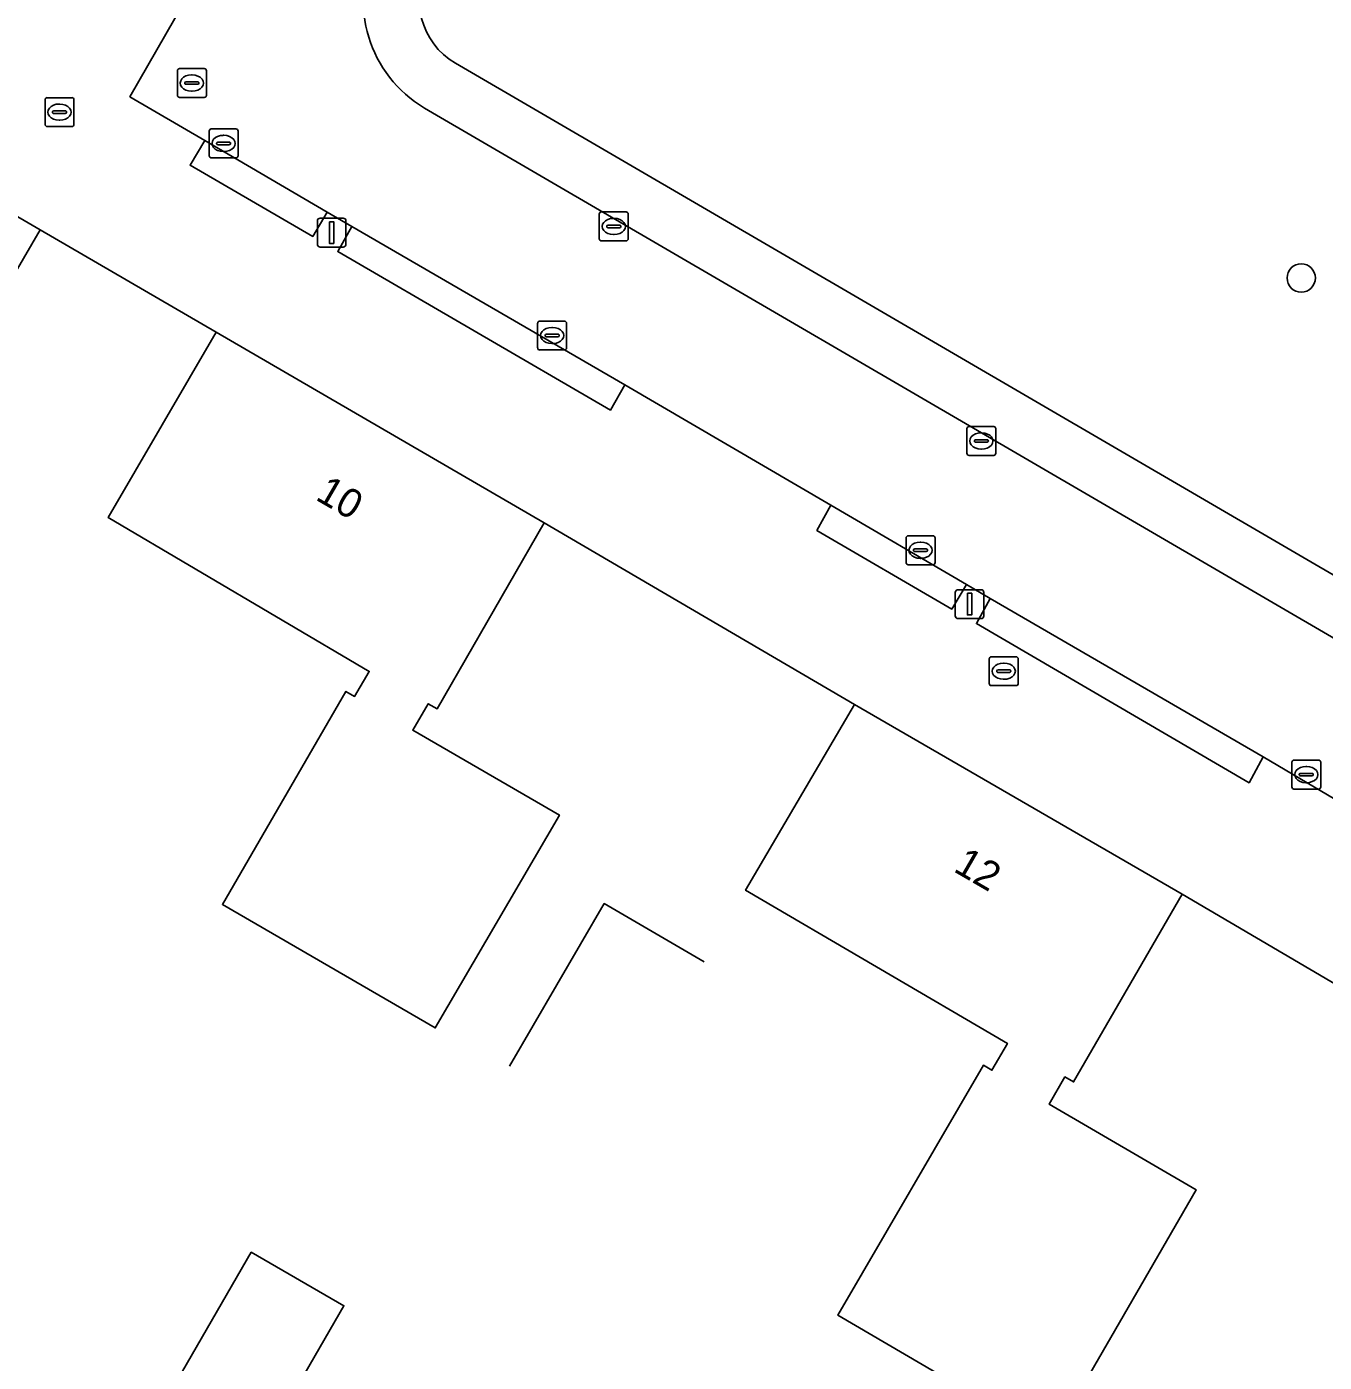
# Model space of a CAD drawing. Extents: x 156502 to 159075, y 384229 to 386100.
# Drawn here: x 157106.1 to 157150.95, y 385818.95 to 385865.1 of the extents above; entities that cross this region are included whole.
import ezdxf

# ---------------------------------------------------------------- set-up
doc = ezdxf.new("R2010")
doc.units = 0
for name, color, linetype in [('IMGEO_Boom', 7, 'Continuous'), ('IMGEO_Erf', 7, 'Continuous'), ('IMGEO_Groenvoorziening', 7, 'Continuous'), ('IMGEO_Haag', 7, 'Continuous'), ('IMGEO_Hek', 7, 'Continuous'), ('IMGEO_Kolk', 7, 'Continuous'), ('IMGEO_Lichtmast', 7, 'Continuous'), ('IMGEO_Muur', 7, 'Continuous'), ('IMGEO_Pand', 7, 'Continuous'), ('IMGEO_Pand_nummerreeks', 7, 'Continuous'), ('IMGEO_Parkeervlak_open', 7, 'Continuous'), ('IMGEO_Rijbaan_lokaal_open', 7, 'Continuous'), ('IMGEO_Rioolput', 7, 'Continuous'), ('IMGEO_Voetpad_open', 7, 'Continuous')]:
    doc.layers.add(name, color=color, linetype=linetype)

msp = doc.modelspace()

# ---------------------------------------------------------------- linework, layer by layer
at = {"layer": 'IMGEO_Boom'}
msp.add_circle((157150.156, 385856.417), 0.489, dxfattribs=at)
at = {"layer": 'IMGEO_Erf'}
msp.add_lwpolyline([(157155.595, 385829.52), (157146.045, 385835.121), (157142.29, 385828.637), (157141.989, 385828.812), (157141.44, 385827.871), (157146.528, 385824.906), (157141.519, 385816.264), (157134.144, 385820.573), (157139.17, 385829.213), (157139.464, 385829.042), (157140.002, 385829.967), (157130.951, 385835.263), (157134.715, 385841.68), (157123.992, 385847.954), (157120.284, 385841.529), (157119.981, 385841.704), (157119.443, 385840.792), (157124.514, 385837.857), (157120.221, 385830.506), (157112.866, 385834.77), (157117.135, 385842.132), (157117.437, 385841.957), (157117.939, 385842.822), (157108.916, 385848.145), (157112.648, 385854.542), (157106.562, 385858.084), (157102.808, 385851.646)], dxfattribs=at)
msp.add_lwpolyline([(157111.485, 385818.64), (157113.86, 385822.753), (157117.067, 385820.902), (157114.692, 385816.789)], close=True, dxfattribs=at)
at = {"layer": 'IMGEO_Groenvoorziening'}
msp.add_lwpolyline([(157120.919, 385863.835), (157175.135, 385832.241)], dxfattribs=at)
for points in [[(157116.486, 385858.694), (157112.261, 385861.167), (157111.749, 385860.312), (157115.987, 385857.851)], [(157117.345, 385858.202), (157116.851, 385857.331), (157126.279, 385851.85), (157126.778, 385852.73)], [(157138.584, 385845.831), (157133.897, 385848.562), (157133.418, 385847.696), (157138.076, 385844.975)], [(157139.408, 385845.347), (157138.927, 385844.474), (157148.354, 385838.978), (157148.842, 385839.867)]]:
    msp.add_lwpolyline(points, close=True, dxfattribs=at)
msp.add_arc((157122.202, 385866.019), 2.533, 149.5838, 239.5596, dxfattribs=at)
at = {"layer": 'IMGEO_Haag'}
for points in [[(157116.486, 385858.694), (157112.261, 385861.167), (157111.749, 385860.312), (157115.987, 385857.851)], [(157117.345, 385858.202), (157116.851, 385857.331), (157126.279, 385851.85), (157126.778, 385852.73)], [(157138.584, 385845.831), (157133.897, 385848.562), (157133.418, 385847.696), (157138.076, 385844.975)], [(157139.408, 385845.347), (157138.927, 385844.474), (157148.354, 385838.978), (157148.842, 385839.867)]]:
    msp.add_lwpolyline(points, close=True, dxfattribs=at)
at = {"layer": 'IMGEO_Hek'}
for points in [[(157112.648, 385854.542), (157106.562, 385858.084)], [(157134.715, 385841.68), (157123.992, 385847.954)], [(157155.595, 385829.52), (157146.045, 385835.121)]]:
    msp.add_lwpolyline(points, dxfattribs=at)
at = {"layer": 'IMGEO_Kolk'}
for p, q in [((157112.407, 385860.641), (157112.407, 385861.493)), ((157112.482, 385861.567), (157113.334, 385861.567)), ((157112.895, 385861.347), (157112.92, 385861.347)), ((157113.408, 385861.493), (157113.408, 385860.641)), ((157112.666, 385861.061), (157112.666, 385861.073)), ((157113.104, 385861.024), (157112.706, 385861.024)), ((157112.709, 385861.11), (157113.107, 385861.11)), ((157113.15, 385861.073), (157113.15, 385861.061)), ((157113.334, 385860.567), (157112.482, 385860.567)), ((157112.918, 385860.787), (157112.893, 385860.787)), ((157125.894, 385857.772), (157125.894, 385858.624)), ((157125.969, 385858.698), (157126.821, 385858.698)), ((157126.895, 385858.624), (157126.895, 385857.772)), ((157126.153, 385858.192), (157126.153, 385858.204)), ((157126.591, 385858.155), (157126.193, 385858.155)), ((157126.196, 385858.241), (157126.594, 385858.241)), ((157126.382, 385858.478), (157126.407, 385858.478)), ((157126.637, 385858.204), (157126.637, 385858.192)), ((157126.821, 385857.698), (157125.969, 385857.698)), ((157126.405, 385857.918), (157126.38, 385857.918)), ((157123.763, 385854.003), (157123.763, 385854.855)), ((157123.838, 385854.929), (157124.69, 385854.929)), ((157124.764, 385854.855), (157124.764, 385854.003)), ((157124.022, 385854.423), (157124.022, 385854.435)), ((157124.46, 385854.386), (157124.062, 385854.386)), ((157124.065, 385854.472), (157124.463, 385854.472)), ((157124.251, 385854.709), (157124.276, 385854.709)), ((157124.506, 385854.435), (157124.506, 385854.423)), ((157124.69, 385853.929), (157123.838, 385853.929)), ((157124.274, 385854.149), (157124.249, 385854.149)), ((157138.599, 385850.359), (157138.599, 385851.211)), ((157138.674, 385851.285), (157139.526, 385851.285)), ((157139.6, 385851.211), (157139.6, 385850.359)), ((157138.858, 385850.779), (157138.858, 385850.791)), ((157139.296, 385850.742), (157138.898, 385850.742)), ((157138.901, 385850.828), (157139.299, 385850.828)), ((157139.087, 385851.065), (157139.112, 385851.065)), ((157139.342, 385850.791), (157139.342, 385850.779)), ((157139.526, 385850.285), (157138.674, 385850.285)), ((157139.11, 385850.505), (157139.085, 385850.505)), ((157136.497, 385846.584), (157136.497, 385847.436)), ((157136.572, 385847.51), (157137.424, 385847.51)), ((157137.498, 385847.436), (157137.498, 385846.584)), ((157136.756, 385847.004), (157136.756, 385847.016)), ((157136.799, 385847.053), (157137.197, 385847.053)), ((157136.985, 385847.29), (157137.01, 385847.29)), ((157137.24, 385847.016), (157137.24, 385847.004)), ((157137.424, 385846.51), (157136.572, 385846.51)), ((157137.194, 385846.967), (157136.796, 385846.967)), ((157137.008, 385846.73), (157136.983, 385846.73)), ((157149.831, 385838.831), (157149.831, 385839.683)), ((157149.906, 385839.757), (157150.758, 385839.757)), ((157150.832, 385839.683), (157150.832, 385838.831)), ((157150.09, 385839.251), (157150.09, 385839.263)), ((157150.528, 385839.214), (157150.13, 385839.214)), ((157150.133, 385839.3), (157150.531, 385839.3)), ((157150.319, 385839.537), (157150.344, 385839.537)), ((157150.574, 385839.263), (157150.574, 385839.251)), ((157150.758, 385838.757), (157149.906, 385838.757)), ((157150.342, 385838.977), (157150.317, 385838.977))]:
    msp.add_line(p, q, dxfattribs=at)
for points in [[(157112.407, 385860.641), (157112.407, 385861.493)], [(157112.482, 385861.567), (157113.334, 385861.567)], [(157113.408, 385861.493), (157113.408, 385860.641)], [(157113.334, 385860.567), (157112.482, 385860.567)], [(157125.894, 385857.772), (157125.894, 385858.624)], [(157125.969, 385858.698), (157126.821, 385858.698)], [(157126.895, 385858.624), (157126.895, 385857.772)], [(157126.821, 385857.698), (157125.969, 385857.698)], [(157123.763, 385854.003), (157123.763, 385854.855)], [(157123.838, 385854.929), (157124.69, 385854.929)], [(157124.764, 385854.855), (157124.764, 385854.003)], [(157124.69, 385853.929), (157123.838, 385853.929)], [(157138.599, 385850.359), (157138.599, 385851.211)], [(157138.674, 385851.285), (157139.526, 385851.285)], [(157139.6, 385851.211), (157139.6, 385850.359)], [(157139.526, 385850.285), (157138.674, 385850.285)], [(157136.497, 385846.584), (157136.497, 385847.436)], [(157136.572, 385847.51), (157137.424, 385847.51)], [(157137.498, 385847.436), (157137.498, 385846.584)], [(157137.424, 385846.51), (157136.572, 385846.51)], [(157149.831, 385838.831), (157149.831, 385839.683)], [(157149.906, 385839.757), (157150.758, 385839.757)], [(157150.832, 385839.683), (157150.832, 385838.831)], [(157150.758, 385838.757), (157149.906, 385838.757)]]:
    msp.add_lwpolyline(points, dxfattribs=at)
for centre, radius, start, end in [((157112.484, 385861.491), 0.0765, 91.552, 178.448), ((157112.484, 385861.491), 0.0765, 91.552, 178.448), ((157113.332, 385861.491), 0.0765, 1.552, 88.448), ((157113.332, 385861.491), 0.0765, 1.552, 88.448), ((157112.706, 385861.07), 0.0403, 85.8775, 175.7526), ((157112.703, 385861.06), 0.0366, 178.938, 274.7102), ((157113.107, 385861.067), 0.043, 264.8664, 352.4533), ((157113.111, 385861.072), 0.0386, 1.7309, 96.639), ((157112.484, 385860.643), 0.0765, 181.552, 268.448), ((157112.484, 385860.643), 0.0765, 181.552, 268.448), ((157113.332, 385860.643), 0.0765, 271.552, 358.448), ((157113.332, 385860.643), 0.0765, 271.552, 358.448), ((157125.971, 385858.622), 0.0765, 91.552, 178.448), ((157125.971, 385858.622), 0.0765, 91.552, 178.448), ((157126.819, 385858.622), 0.0765, 1.552, 88.448), ((157126.819, 385858.622), 0.0765, 1.552, 88.448), ((157126.193, 385858.201), 0.0403, 85.8775, 175.7526), ((157126.19, 385858.191), 0.0366, 178.938, 274.7102), ((157126.594, 385858.198), 0.043, 264.8664, 352.4533), ((157126.598, 385858.203), 0.0386, 1.7309, 96.639), ((157125.971, 385857.774), 0.0765, 181.552, 268.448), ((157125.971, 385857.774), 0.0765, 181.552, 268.448), ((157126.819, 385857.774), 0.0765, 271.552, 358.448), ((157126.819, 385857.774), 0.0765, 271.552, 358.448), ((157123.84, 385854.853), 0.0765, 91.552, 178.448), ((157123.84, 385854.853), 0.0765, 91.552, 178.448), ((157124.688, 385854.853), 0.0765, 1.552, 88.448), ((157124.688, 385854.853), 0.0765, 1.552, 88.448), ((157124.062, 385854.432), 0.0403, 85.8775, 175.7526), ((157124.059, 385854.422), 0.0366, 178.938, 274.7102), ((157124.463, 385854.429), 0.043, 264.8664, 352.4533), ((157124.467, 385854.434), 0.0386, 1.7309, 96.639), ((157123.84, 385854.005), 0.0765, 181.552, 268.448), ((157123.84, 385854.005), 0.0765, 181.552, 268.448), ((157124.688, 385854.005), 0.0765, 271.552, 358.448), ((157124.688, 385854.005), 0.0765, 271.552, 358.448), ((157138.676, 385851.209), 0.0765, 91.552, 178.448), ((157138.676, 385851.209), 0.0765, 91.552, 178.448), ((157139.524, 385851.209), 0.0765, 1.552, 88.448), ((157139.524, 385851.209), 0.0765, 1.552, 88.448), ((157138.898, 385850.788), 0.0403, 85.8775, 175.7526), ((157138.895, 385850.778), 0.0366, 178.938, 274.7102), ((157139.299, 385850.785), 0.043, 264.8664, 352.4533), ((157139.303, 385850.79), 0.0386, 1.7309, 96.639), ((157138.676, 385850.361), 0.0765, 181.552, 268.448), ((157138.676, 385850.361), 0.0765, 181.552, 268.448), ((157139.524, 385850.361), 0.0765, 271.552, 358.448), ((157139.524, 385850.361), 0.0765, 271.552, 358.448), ((157136.574, 385847.434), 0.0765, 91.552, 178.448), ((157136.574, 385847.434), 0.0765, 91.552, 178.448), ((157137.422, 385847.434), 0.0765, 1.552, 88.448), ((157137.422, 385847.434), 0.0765, 1.552, 88.448), ((157136.796, 385847.013), 0.0403, 85.8775, 175.7526), ((157136.793, 385847.003), 0.0366, 178.938, 274.7102), ((157137.197, 385847.01), 0.043, 264.8664, 352.4533), ((157137.201, 385847.015), 0.0386, 1.7309, 96.639), ((157136.574, 385846.586), 0.0765, 181.552, 268.448), ((157136.574, 385846.586), 0.0765, 181.552, 268.448), ((157137.422, 385846.586), 0.0765, 271.552, 358.448), ((157137.422, 385846.586), 0.0765, 271.552, 358.448), ((157149.908, 385839.681), 0.0765, 91.552, 178.448), ((157149.908, 385839.681), 0.0765, 91.552, 178.448), ((157150.756, 385839.681), 0.0765, 1.552, 88.448), ((157150.756, 385839.681), 0.0765, 1.552, 88.448), ((157150.13, 385839.26), 0.0403, 85.8775, 175.7526), ((157150.127, 385839.25), 0.0366, 178.938, 274.7102), ((157150.531, 385839.257), 0.043, 264.8664, 352.4533), ((157150.535, 385839.262), 0.0386, 1.7309, 96.639), ((157149.908, 385838.833), 0.0765, 181.552, 268.448), ((157149.908, 385838.833), 0.0765, 181.552, 268.448), ((157150.756, 385838.833), 0.0765, 271.552, 358.448), ((157150.756, 385838.833), 0.0765, 271.552, 358.448)]:
    msp.add_arc(centre, radius, start, end, dxfattribs=at)
for centre, major_axis, ratio, start_param, end_param in [((157112.894, 385861.067), (-0.387, 0.002), 0.722429, 4.712389, 7.853982), ((157112.919, 385861.067), (-0.39, 0.002), 0.717154, 1.570796, 4.712389), ((157126.381, 385858.198), (-0.387, 0.002), 0.722429, 4.712389, 7.853982), ((157126.406, 385858.198), (-0.39, 0.002), 0.717154, 1.570796, 4.712389), ((157124.25, 385854.429), (-0.387, 0.002), 0.722429, 4.712389, 7.853982), ((157124.275, 385854.429), (-0.39, 0.002), 0.717154, 1.570796, 4.712389), ((157139.086, 385850.785), (-0.387, 0.002), 0.722429, 4.712389, 7.853982), ((157139.111, 385850.785), (-0.39, 0.002), 0.717154, 1.570796, 4.712389), ((157136.984, 385847.01), (-0.387, 0.002), 0.722429, 4.712389, 7.853982), ((157137.009, 385847.01), (-0.39, 0.002), 0.717154, 1.570796, 4.712389), ((157150.318, 385839.257), (-0.387, 0.002), 0.722429, 4.712389, 7.853982), ((157150.343, 385839.257), (-0.39, 0.002), 0.717154, 1.570796, 4.712389)]:
    msp.add_ellipse(centre, major_axis=major_axis, ratio=ratio, start_param=start_param, end_param=end_param, dxfattribs=at)
at = {"layer": 'IMGEO_Lichtmast'}
for p, q in [((157116.147, 385857.585), (157116.147, 385858.385)), ((157116.147, 385858.385), (157116.147, 385857.585)), ((157116.247, 385858.485), (157117.037, 385858.485)), ((157117.037, 385858.485), (157116.247, 385858.485)), ((157117.137, 385858.385), (157117.137, 385857.585)), ((157117.137, 385857.585), (157117.137, 385858.385)), ((157117.037, 385857.485), (157116.247, 385857.485)), ((157116.247, 385857.485), (157117.037, 385857.485)), ((157138.297, 385845.647), (157139.087, 385845.647)), ((157139.087, 385845.647), (157138.297, 385845.647)), ((157138.197, 385844.747), (157138.197, 385845.547)), ((157138.197, 385845.547), (157138.197, 385844.747)), ((157139.187, 385845.547), (157139.187, 385844.747)), ((157139.187, 385844.747), (157139.187, 385845.547)), ((157139.087, 385844.647), (157138.297, 385844.647)), ((157138.297, 385844.647), (157139.087, 385844.647))]:
    msp.add_line(p, q, dxfattribs=at)
for points in [[(157116.567, 385858.36), (157116.717, 385858.36), (157116.717, 385857.61), (157116.567, 385857.61), (157116.567, 385858.36)], [(157138.617, 385845.522), (157138.767, 385845.522), (157138.767, 385844.772), (157138.617, 385844.772), (157138.617, 385845.522)]]:
    msp.add_lwpolyline(points, dxfattribs=at)
for centre, start, end in [((157116.247, 385858.385), 90, 180), ((157116.247, 385858.385), 90, 180), ((157117.037, 385858.385), 0, 90), ((157117.037, 385858.385), 360, 90), ((157116.247, 385857.585), 180, 270), ((157116.247, 385857.585), 180, 270), ((157117.037, 385857.585), 270, 0), ((157117.037, 385857.585), 270, 0), ((157138.297, 385845.547), 90, 180), ((157138.297, 385845.547), 90, 180), ((157139.087, 385845.547), 0, 90), ((157139.087, 385845.547), 360, 90), ((157138.297, 385844.747), 180, 270), ((157138.297, 385844.747), 180, 270), ((157139.087, 385844.747), 270, 0), ((157139.087, 385844.747), 270, 0)]:
    msp.add_arc(centre, 0.1, start, end, dxfattribs=at)
at = {"layer": 'IMGEO_Muur'}
msp.add_lwpolyline([(157122.793, 385829.183), (157126.065, 385834.799), (157129.521, 385832.785)], dxfattribs=at)
at = {"layer": 'IMGEO_Pand'}
for points in [[(157100.836, 385861.41), (157100.545, 385861.579), (157094.927, 385864.842), (157098.324, 385870.649), (157093.153, 385873.673), (157086.085, 385861.587), (157091.192, 385858.41), (157091.477, 385858.867), (157093.801, 385857.507), (157093.53, 385857.04), (157102.808, 385851.646), (157106.562, 385858.084)], [(157120.221, 385830.506), (157124.514, 385837.857), (157119.443, 385840.792), (157119.981, 385841.704), (157120.284, 385841.529), (157123.992, 385847.954), (157112.648, 385854.542), (157108.916, 385848.145), (157117.939, 385842.822), (157117.437, 385841.957), (157117.135, 385842.132), (157112.866, 385834.77)], [(157134.715, 385841.68), (157130.951, 385835.263), (157140.002, 385829.967), (157139.464, 385829.042), (157139.17, 385829.213), (157134.144, 385820.573), (157141.519, 385816.264), (157146.528, 385824.906), (157141.44, 385827.871), (157141.989, 385828.812), (157142.29, 385828.637), (157146.045, 385835.121)], [(157111.485, 385818.64), (157114.692, 385816.789), (157117.067, 385820.902), (157113.86, 385822.753)]]:
    msp.add_lwpolyline(points, close=True, dxfattribs=at)
at = {"layer": 'IMGEO_Parkeervlak_open'}
for points in [[(157175.135, 385832.241), (157120.919, 385863.835)], [(157119.853, 385862.285), (157174.491, 385830.448)]]:
    msp.add_lwpolyline(points, dxfattribs=at)
for centre, radius, start, end in [((157122.079, 385866.021), 4.349, 155.0271, 239.2073), ((157122.202, 385866.019), 2.533, 149.5838, 239.5596)]:
    msp.add_arc(centre, radius, start, end, dxfattribs=at)
at = {"layer": 'IMGEO_Rijbaan_lokaal_open'}
for points in [[(157112.461, 385867.56), (157109.666, 385862.678), (157112.261, 385861.167), (157116.486, 385858.694), (157117.345, 385858.202), (157126.778, 385852.73), (157133.897, 385848.562), (157138.584, 385845.831), (157139.408, 385845.347), (157148.842, 385839.867), (157155.57, 385835.897), (157159.377, 385833.674), (157160.239, 385833.196), (157169.662, 385827.706), (157174.449, 385824.915), (157176.957, 385823.481), (157177.826, 385822.969), (157181.039, 385821.079), (157185.809, 385818.305)], [(157174.491, 385830.448), (157119.853, 385862.285)]]:
    msp.add_lwpolyline(points, dxfattribs=at)
msp.add_arc((157122.079, 385866.021), 4.349, 155.0271, 239.2073, dxfattribs=at)
at = {"layer": 'IMGEO_Rioolput'}
for p, q in [((157111.385, 385863.654), (157112.237, 385863.654)), ((157111.31, 385862.728), (157111.31, 385863.58)), ((157111.569, 385863.148), (157111.569, 385863.16)), ((157111.612, 385863.197), (157112.01, 385863.197)), ((157111.798, 385863.434), (157111.823, 385863.434)), ((157112.053, 385863.16), (157112.053, 385863.148)), ((157112.311, 385863.58), (157112.311, 385862.728)), ((157112.007, 385863.111), (157111.609, 385863.111)), ((157111.821, 385862.874), (157111.796, 385862.874)), ((157106.734, 385861.722), (157106.734, 385862.574)), ((157106.809, 385862.648), (157107.661, 385862.648)), ((157107.222, 385862.428), (157107.247, 385862.428)), ((157107.735, 385862.574), (157107.735, 385861.722)), ((157112.237, 385862.654), (157111.385, 385862.654)), ((157106.993, 385862.142), (157106.993, 385862.154)), ((157107.431, 385862.105), (157107.033, 385862.105)), ((157107.036, 385862.191), (157107.434, 385862.191)), ((157107.245, 385861.868), (157107.22, 385861.868)), ((157107.477, 385862.154), (157107.477, 385862.142)), ((157107.661, 385861.648), (157106.809, 385861.648)), ((157139.448, 385843.331), (157140.3, 385843.331)), ((157139.373, 385842.405), (157139.373, 385843.257)), ((157139.632, 385842.825), (157139.632, 385842.837)), ((157139.675, 385842.874), (157140.073, 385842.874)), ((157139.861, 385843.111), (157139.886, 385843.111)), ((157140.116, 385842.837), (157140.116, 385842.825)), ((157140.374, 385843.257), (157140.374, 385842.405)), ((157140.07, 385842.788), (157139.672, 385842.788)), ((157139.884, 385842.551), (157139.859, 385842.551)), ((157140.3, 385842.331), (157139.448, 385842.331))]:
    msp.add_line(p, q, dxfattribs=at)
for points in [[(157111.385, 385863.654), (157112.237, 385863.654)], [(157111.31, 385862.728), (157111.31, 385863.58)], [(157112.311, 385863.58), (157112.311, 385862.728)], [(157106.734, 385861.722), (157106.734, 385862.574)], [(157106.809, 385862.648), (157107.661, 385862.648)], [(157107.735, 385862.574), (157107.735, 385861.722)], [(157112.237, 385862.654), (157111.385, 385862.654)], [(157107.661, 385861.648), (157106.809, 385861.648)], [(157139.448, 385843.331), (157140.3, 385843.331)], [(157139.373, 385842.405), (157139.373, 385843.257)], [(157140.374, 385843.257), (157140.374, 385842.405)], [(157140.3, 385842.331), (157139.448, 385842.331)]]:
    msp.add_lwpolyline(points, dxfattribs=at)
for centre, radius, start, end in [((157111.387, 385863.578), 0.0765, 91.552, 178.448), ((157111.387, 385863.578), 0.0765, 91.552, 178.448), ((157112.235, 385863.578), 0.0765, 1.552, 88.448), ((157112.235, 385863.578), 0.0765, 1.552, 88.448), ((157111.609, 385863.157), 0.0403, 85.8775, 175.7526), ((157111.606, 385863.147), 0.0366, 178.938, 274.7102), ((157112.01, 385863.154), 0.043, 264.8664, 352.4533), ((157112.014, 385863.159), 0.0386, 1.7309, 96.639), ((157111.387, 385862.73), 0.0765, 181.552, 268.448), ((157111.387, 385862.73), 0.0765, 181.552, 268.448), ((157112.235, 385862.73), 0.0765, 271.552, 358.448), ((157112.235, 385862.73), 0.0765, 271.552, 358.448), ((157106.811, 385862.572), 0.0765, 91.552, 178.448), ((157106.811, 385862.572), 0.0765, 91.552, 178.448), ((157107.659, 385862.572), 0.0765, 1.552, 88.448), ((157107.659, 385862.572), 0.0765, 1.552, 88.448), ((157107.033, 385862.151), 0.0403, 85.8775, 175.7526), ((157107.03, 385862.141), 0.0366, 178.938, 274.7102), ((157107.434, 385862.148), 0.043, 264.8664, 352.4533), ((157107.438, 385862.153), 0.0386, 1.7309, 96.639), ((157106.811, 385861.724), 0.0765, 181.552, 268.448), ((157106.811, 385861.724), 0.0765, 181.552, 268.448), ((157107.659, 385861.724), 0.0765, 271.552, 358.448), ((157107.659, 385861.724), 0.0765, 271.552, 358.448), ((157139.45, 385843.255), 0.0765, 91.552, 178.448), ((157139.45, 385843.255), 0.0765, 91.552, 178.448), ((157140.298, 385843.255), 0.0765, 1.552, 88.448), ((157140.298, 385843.255), 0.0765, 1.552, 88.448), ((157139.672, 385842.834), 0.0403, 85.8775, 175.7526), ((157139.669, 385842.824), 0.0366, 178.938, 274.7102), ((157140.073, 385842.831), 0.043, 264.8664, 352.4533), ((157140.077, 385842.836), 0.0386, 1.7309, 96.639), ((157139.45, 385842.407), 0.0765, 181.552, 268.448), ((157139.45, 385842.407), 0.0765, 181.552, 268.448), ((157140.298, 385842.407), 0.0765, 271.552, 358.448), ((157140.298, 385842.407), 0.0765, 271.552, 358.448)]:
    msp.add_arc(centre, radius, start, end, dxfattribs=at)
for centre, major_axis, ratio, start_param, end_param in [((157111.797, 385863.154), (-0.387, 0.002), 0.722429, 4.712389, 7.853982), ((157111.822, 385863.154), (-0.39, 0.002), 0.717154, 1.570796, 4.712389), ((157107.221, 385862.148), (-0.387, 0.002), 0.722429, 4.712389, 7.853982), ((157107.246, 385862.148), (-0.39, 0.002), 0.717154, 1.570796, 4.712389), ((157139.86, 385842.831), (-0.387, 0.002), 0.722429, 4.712389, 7.853982), ((157139.885, 385842.831), (-0.39, 0.002), 0.717154, 1.570796, 4.712389)]:
    msp.add_ellipse(centre, major_axis=major_axis, ratio=ratio, start_param=start_param, end_param=end_param, dxfattribs=at)
at = {"layer": 'IMGEO_Voetpad_open'}
for points in [[(157116.16, 385883.109), (157114.16, 385884.269), (157111.651, 385879.994), (157106.141, 385870.607), (157105.837, 385870.09), (157105.698, 385869.85), (157102.227, 385863.854), (157101.95, 385864.014), (157100.545, 385861.579), (157100.836, 385861.41), (157106.562, 385858.084), (157112.648, 385854.542), (157123.992, 385847.954), (157134.715, 385841.68), (157146.045, 385835.121), (157155.595, 385829.52), (157159.85, 385827.054), (157183.031, 385813.57)], [(157155.57, 385835.897), (157148.842, 385839.867), (157148.354, 385838.978), (157138.927, 385844.474), (157139.408, 385845.347), (157138.584, 385845.831), (157138.076, 385844.975), (157133.418, 385847.696), (157133.897, 385848.562), (157126.778, 385852.73), (157126.279, 385851.85), (157116.851, 385857.331), (157117.345, 385858.202), (157116.486, 385858.694), (157115.987, 385857.851), (157111.749, 385860.312), (157112.261, 385861.167), (157109.666, 385862.678), (157112.461, 385867.56)]]:
    msp.add_lwpolyline(points, dxfattribs=at)

# ---------------------------------------------------------------- texts
at = {"layer": 'IMGEO_Pand_nummerreeks'}
for s, rotation, p in [('10', 329.8534, (157116.045, 385848.776)), ('12', 329.9336, (157138.097, 385835.932))]:
    msp.add_text(s, height=1, rotation=rotation, dxfattribs=at).set_placement(p)

doc.saveas('drawing.dxf')
